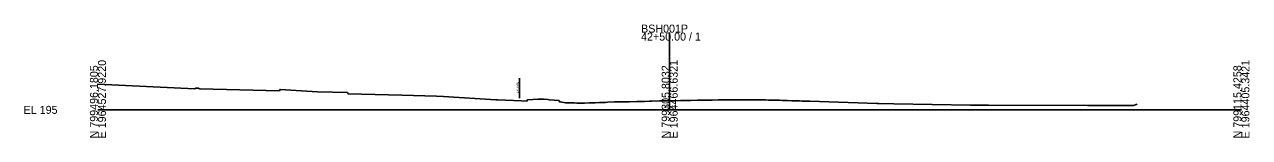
# Model space of a CAD drawing. Extents: x -26 to 1403, y -10 to 19587.
# Drawn here: x 974.3 to 1402.8, y 6490.3 to 6529.9 of the extents above; entities that cross this region are included whole.
import ezdxf

# ---------------------------------------------------------------- set-up
doc = ezdxf.new("R2010")
doc.units = 0
for name, color, linetype in [('Default', 7, 'Continuous'), ('RD_GPK_XS_Cell', 7, 'Continuous'), ('RD_XS_ExGround', 7, 'Continuous'), ('RD_XS_ExRW', 7, 'Continuous'), ('RD_XS_TX_Elev_EX', 7, 'Continuous')]:
    doc.layers.add(name, color=color, linetype=linetype)

msp = doc.modelspace()

# ---------------------------------------------------------------- linework, layer by layer
at = {"layer": 'RD_GPK_XS_Cell'}
for p, q in [((1200, 6500), (1200, 6527.05)), ((1000, 6500), (1200, 6500)), ((1200, 6500), (1400, 6500))]:
    msp.add_line(p, q, dxfattribs=at)
at = {"layer": 'RD_XS_ExGround'}
msp.add_lwpolyline([(1000, 6509.02), (1033.87, 6507.39), (1034.26, 6507.54), (1035.05, 6507.55), (1035.6, 6507.35), (1063.5, 6506.7), (1063.74, 6507.15), (1076.76, 6506.33), (1087.29, 6506.05), (1087.54, 6505.59), (1106.31, 6505.16), (1118.39, 6504.74), (1120.93, 6504.62), (1139.16, 6503.54), (1139.81, 6503.52), (1148.14, 6503.1), (1150.07, 6503.07), (1150.32, 6503.52), (1154.04, 6503.71), (1154.77, 6503.72), (1155.72, 6503.71), (1156.15, 6503.69), (1157.42, 6503.62), (1157.89, 6503.56), (1159.62, 6503.43), (1161.26, 6503.29), (1161.43, 6502.84), (1161.8, 6502.79), (1162.32, 6502.67), (1163.07, 6502.52), (1163.58, 6502.51), (1164.94, 6502.45), (1166.55, 6502.4), (1167.53, 6502.37), (1167.83, 6502.36), (1168.49, 6502.33), (1168.82, 6502.32), (1169.22, 6502.31), (1170.18, 6502.35), (1171.96, 6502.41), (1172.8, 6502.44), (1173.95, 6502.48), (1175.43, 6502.54), (1175.95, 6502.56), (1177.52, 6502.62), (1178.24, 6502.65), (1180.65, 6502.75), (1182.33, 6502.78), (1183.27, 6502.79), (1185.99, 6502.84), (1188.52, 6502.91), (1189.88, 6502.94), (1191.14, 6502.98), (1192.95, 6503.03), (1193.47, 6503.05), (1193.77, 6503.05), (1196.39, 6503.1), (1197.75, 6503.11), (1199.03, 6503.13), (1200, 6503.15), (1201.91, 6503.19), (1203.74, 6503.24), (1204.31, 6503.26), (1206.55, 6503.31), (1207.29, 6503.33), (1209.71, 6503.36), (1210.16, 6503.36), (1211.7, 6503.38), (1212.19, 6503.38), (1213.15, 6503.39), (1214.82, 6503.41), (1217.02, 6503.45), (1217.66, 6503.46), (1219.03, 6503.48), (1220.04, 6503.51), (1220.87, 6503.5), (1222.66, 6503.49), (1224.75, 6503.48), (1225.57, 6503.48), (1226.44, 6503.47), (1227.55, 6503.47), (1227.91, 6503.48), (1231.02, 6503.5), (1233.17, 6503.46), (1233.51, 6503.46), (1234.55, 6503.43), (1235.8, 6503.4), (1237.47, 6503.36), (1238.41, 6503.34), (1239.5, 6503.3), (1241.05, 6503.25), (1242.71, 6503.18), (1243.67, 6503.14), (1245.45, 6503.1), (1246.3, 6503.07), (1247.78, 6503.04), (1249.08, 6502.99), (1272.49, 6502.27), (1273.14, 6502.25), (1278.44, 6502.13), (1305.28, 6501.68), (1311.59, 6501.59), (1346.21, 6501.5), (1362.27, 6501.54), (1363.6, 6501.97)], dxfattribs=at)
at = {"layer": 'RD_XS_ExRW'}
msp.add_line((1147.45, 6504.14), (1147.45, 6511.14), dxfattribs=at)

# ---------------------------------------------------------------- texts
at = {"layer": 'Default'}
msp.add_text('-', height=0.0001, dxfattribs=at).set_placement((1000, 6500))
at = {"layer": 'RD_GPK_XS_Cell'}
for s, p in [('42+50.00 / 1', (1190, 6524.25)), ('BSH001P', (1190, 6527.05)), ('EL 195', (974, 6498.6))]:
    msp.add_text(s, height=2.8, dxfattribs=at).set_placement(p)
for s, p in [('N 799496.1805', (1000, 6490)), ('E 1964527.9220', (1002.8, 6490)), ('N 799305.8032', (1200, 6490)), ('E 1964466.6321', (1202.8, 6490)), ('N 799115.4258', (1400, 6490)), ('E 1964405.3421', (1402.8, 6490))]:
    msp.add_text(s, height=2.8, rotation=90, dxfattribs=at).set_placement(p)
at = {"layer": 'RD_XS_ExRW'}
msp.add_text('EX. R/W ', height=0.75, rotation=90, dxfattribs=at).set_placement((1147.2, 6505.81))
at = {"layer": 'RD_XS_TX_Elev_EX'}
msp.add_text('198.15', height=1, dxfattribs=at).set_placement((1197.95, 6500.65))

doc.saveas('drawing.dxf')
